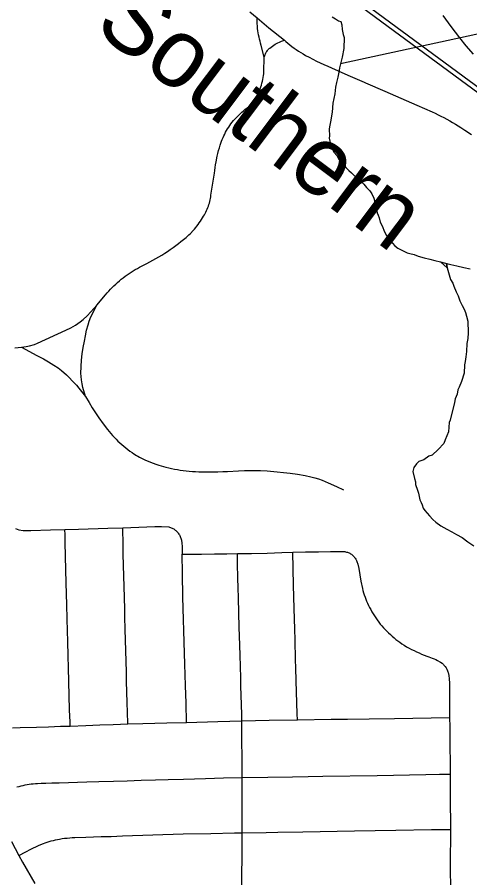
# Model space of a CAD drawing. Extents: x 0 to 34, y -1.2 to 22.
# Drawn here: x 6.951 to 7.322, y 18.066 to 18.774 of the extents above; entities that cross this region are included whole.
import ezdxf

# ---------------------------------------------------------------- set-up
doc = ezdxf.new("R2010")
doc.units = 0
for name, color, linetype in [('GM_X_City_Street', 7, 'Continuous'), ('GM_X_County_Road', 7, 'Continuous'), ('GM_X_Rail_Line', 7, 'Continuous'), ('GM_X_Rail_Line_Text', 7, 'Continuous'), ('GM_X_State_Route', 7, 'Continuous'), ('SH_Border', 7, 'Continuous'), ('SH_Data', 7, 'Continuous')]:
    doc.layers.add(name, color=color, linetype=linetype)

msp = doc.modelspace()

# ---------------------------------------------------------------- linework, layer by layer
at = {"layer": 'GM_X_City_Street'}
for points in [[(7.15357, 18.74058), (7.15114, 18.75038), (7.15065, 18.75207), (7.15018, 18.75376), (7.14976, 18.75546), (7.14937, 18.75717), (7.14902, 18.75889), (7.14871, 18.76062), (7.14844, 18.76235), (7.14821, 18.76409), (7.14801, 18.76583), (7.14781, 18.76858), (7.14768, 18.77296)], [(6.94876, 18.50187), (6.95415, 18.5024), (6.9581, 18.50301), (6.96084, 18.50352), (6.96487, 18.50464), (6.96748, 18.50559), (6.99072, 18.51625), (6.99482, 18.51826), (6.99872, 18.52057), (7.00246, 18.52317), (7.00482, 18.52506), (7.00816, 18.52814), (7.01128, 18.53145), (7.01601, 18.53697), (7.02321, 18.54547), (7.02454, 18.54699), (7.02589, 18.54849), (7.02728, 18.54995), (7.02869, 18.55139), (7.03014, 18.5528), (7.0316, 18.55419), (7.0331, 18.55555), (7.03462, 18.55687), (7.03617, 18.55816), (7.03774, 18.55942), (7.03934, 18.56062), (7.04096, 18.56178), (7.0426, 18.56291), (7.04426, 18.564), (7.04595, 18.56506), (7.04766, 18.56608), (7.04939, 18.56707), (7.05115, 18.56802), (7.05724, 18.57108), (7.05975, 18.5724), (7.06224, 18.57376), (7.0647, 18.57515), (7.06715, 18.57658), (7.06957, 18.57806), (7.07197, 18.57957), (7.07424, 18.58107), (7.07649, 18.58261), (7.0787, 18.58418), (7.0809, 18.58579), (7.08307, 18.58744), (7.08521, 18.58912), (7.08732, 18.59084), (7.08941, 18.59259), (7.09062, 18.59365), (7.09181, 18.59475), (7.09296, 18.59588), (7.0952, 18.59821), (7.09628, 18.59942), (7.09732, 18.60066), (7.09833, 18.60191), (7.09932, 18.60319), (7.10027, 18.6045), (7.10119, 18.60583), (7.10208, 18.60718), (7.10294, 18.60855), (7.10376, 18.60994), (7.10443, 18.61108), (7.10507, 18.61223), (7.10567, 18.6134), (7.10624, 18.61459), (7.10677, 18.6158), (7.10727, 18.61702), (7.10773, 18.61827), (7.10815, 18.61952), (7.10854, 18.62078), (7.10888, 18.62206), (7.10919, 18.62335), (7.10946, 18.62465), (7.10969, 18.62595), (7.10988, 18.62726), (7.11269, 18.64527), (7.11299, 18.64762), (7.11333, 18.64996), (7.1137, 18.6523), (7.11411, 18.65464), (7.11505, 18.65928), (7.11558, 18.66159), (7.11614, 18.66389), (7.11674, 18.66619), (7.11739, 18.66847), (7.11792, 18.67001), (7.1185, 18.67154), (7.11911, 18.67305), (7.11976, 18.67456), (7.12045, 18.67604), (7.12117, 18.6775), (7.12193, 18.67895), (7.12272, 18.68038), (7.12355, 18.68179), (7.12441, 18.68317), (7.12531, 18.68454), (7.12624, 18.68588), (7.1272, 18.6872), (7.12845, 18.68864), (7.12973, 18.69005), (7.13105, 18.69144), (7.13239, 18.69279), (7.13377, 18.6941), (7.13517, 18.69539), (7.13661, 18.69664), (7.13808, 18.69786), (7.13957, 18.69904), (7.14109, 18.70019), (7.14395, 18.70285), (7.14461, 18.70354), (7.14523, 18.70426), (7.14583, 18.70501), (7.14639, 18.70578), (7.14692, 18.70658), (7.14741, 18.70739), (7.14786, 18.70823), (7.14828, 18.70908), (7.14866, 18.70996), (7.14986, 18.71323), (7.15038, 18.71473), (7.15086, 18.71624), (7.15131, 18.71777), (7.15171, 18.7193), (7.15209, 18.72085), (7.15242, 18.7224), (7.15271, 18.72396), (7.15296, 18.72553), (7.15317, 18.72711), (7.15334, 18.72869), (7.15357, 18.74058), (7.15399, 18.74205), (7.15426, 18.74276), (7.15456, 18.74346), (7.15491, 18.74414), (7.15529, 18.7448), (7.15572, 18.74543), (7.15617, 18.74604), (7.15666, 18.74663), (7.15718, 18.74718), (7.15774, 18.74771), (7.15832, 18.7482), (7.15933, 18.74901), (7.16038, 18.74979), (7.16146, 18.75053), (7.16256, 18.75123), (7.16368, 18.75188), (7.16483, 18.75249), (7.16622, 18.75311), (7.16785, 18.75374), (7.17014, 18.75456)], [(7.00687, 18.46178), (7.0046, 18.4693), (7.00395, 18.47238), (7.00347, 18.47548), (7.0031, 18.48089), (7.00344, 18.49172), (7.00408, 18.49691), (7.00491, 18.50208), (7.00594, 18.50722), (7.00676, 18.51177), (7.00775, 18.51629), (7.00889, 18.52077), (7.00973, 18.52366), (7.01125, 18.52727), (7.01601, 18.53697)], [(6.95415, 18.5024), (6.96686, 18.49553), (6.97219, 18.49277), (6.97652, 18.49032), (6.98075, 18.48772), (6.98428, 18.48532), (6.9871, 18.48315), (6.99112, 18.47963), (6.99364, 18.47711), (6.996, 18.47471), (6.99929, 18.47125), (7.00145, 18.46882), (7.00687, 18.46178), (7.00971, 18.45681), (7.01224, 18.45252), (7.01498, 18.44845), (7.01785, 18.44436), (7.02134, 18.4395), (7.02496, 18.43473), (7.02766, 18.43142), (7.02906, 18.4298), (7.0305, 18.42823), (7.03198, 18.42669), (7.0335, 18.42518), (7.03508, 18.42373), (7.03668, 18.42232), (7.03831, 18.42094), (7.03997, 18.4196), (7.04165, 18.41828), (7.04335, 18.41699), (7.04508, 18.41573), (7.0466, 18.41473), (7.04865, 18.41348), (7.0497, 18.41286), (7.05128, 18.41199), (7.05289, 18.41116), (7.05453, 18.41037), (7.05618, 18.40963), (7.05979, 18.40808), (7.06162, 18.40737), (7.06531, 18.40604), (7.06718, 18.40543), (7.07095, 18.40432), (7.07285, 18.40381), (7.07519, 18.40325), (7.07755, 18.40273), (7.07991, 18.40225), (7.08228, 18.40182), (7.08466, 18.40143), (7.08704, 18.4011), (7.08944, 18.4008), (7.09203, 18.40053), (7.09464, 18.40031), (7.09724, 18.40012), (7.09985, 18.39999), (7.10246, 18.39989), (7.11559, 18.39995), (7.11955, 18.40009), (7.1235, 18.40026), (7.13238, 18.40074), (7.13729, 18.40094), (7.14221, 18.4011), (7.15048, 18.401), (7.15598, 18.40074), (7.15873, 18.40055), (7.1641, 18.40004), (7.16947, 18.39946), (7.17484, 18.39882), (7.18105, 18.39793), (7.18723, 18.39687), (7.1919, 18.39593), (7.19504, 18.39512), (7.19814, 18.39415), (7.20119, 18.39303), (7.20621, 18.39083), (7.21297, 18.38782), (7.21874, 18.38526)], [(6.94931, 18.35333), (6.95201, 18.35225), (6.95562, 18.35172), (6.96198, 18.3518), (6.97804, 18.35221), (6.98985, 18.35246), (7.00111, 18.35287), (7.02517, 18.35368), (7.03736, 18.35401), (7.06379, 18.35491), (7.06911, 18.35501), (7.07521, 18.35479), (7.07592, 18.35458), (7.07662, 18.35433), (7.07729, 18.35405), (7.07796, 18.35373), (7.0786, 18.35338), (7.07923, 18.35299), (7.07984, 18.35257), (7.08043, 18.35212), (7.08098, 18.35164), (7.08206, 18.3506), (7.08257, 18.35003), (7.08306, 18.34944), (7.08351, 18.34882), (7.08392, 18.34817), (7.0843, 18.3475), (7.08464, 18.34682), (7.08494, 18.34611), (7.0852, 18.34539), (7.08543, 18.34466), (7.0856, 18.34391), (7.08574, 18.34316), (7.08589, 18.34192), (7.08602, 18.34074), (7.0861, 18.33922), (7.08619, 18.33227), (7.10209, 18.33237), (7.11289, 18.33247), (7.12286, 18.3326), (7.13158, 18.33273), (7.1432, 18.33292), (7.15595, 18.33324), (7.16811, 18.33363), (7.17697, 18.33391), (7.18761, 18.33414), (7.19812, 18.33433), (7.20795, 18.33447), (7.21759, 18.33458), (7.21905, 18.33449), (7.21978, 18.33439), (7.22049, 18.33424), (7.22121, 18.33406), (7.2219, 18.33385), (7.22259, 18.3336), (7.22327, 18.33331), (7.22392, 18.33298), (7.22456, 18.33263), (7.22518, 18.33224), (7.22578, 18.33176), (7.22634, 18.33125), (7.22688, 18.33071), (7.22739, 18.33015), (7.22788, 18.32955), (7.22832, 18.32894), (7.22874, 18.3283), (7.22947, 18.32696), (7.23004, 18.32555), (7.23028, 18.32482), (7.23047, 18.32408), (7.23123, 18.32038), (7.233, 18.31005), (7.2342, 18.30411), (7.23469, 18.30234), (7.23521, 18.30057), (7.23578, 18.29881), (7.23638, 18.29707), (7.23702, 18.29535), (7.23769, 18.29363), (7.2384, 18.29194), (7.23915, 18.29025), (7.2401, 18.28848), (7.24108, 18.28673), (7.24209, 18.28501), (7.24314, 18.2833), (7.24422, 18.28161), (7.24534, 18.27994), (7.24893, 18.27487), (7.24974, 18.27393), (7.25022, 18.27336), (7.25156, 18.27188), (7.25293, 18.27042), (7.25433, 18.26899), (7.25576, 18.26759), (7.25722, 18.26622), (7.25871, 18.26489), (7.26023, 18.26358), (7.26178, 18.26231), (7.26335, 18.26107), (7.26495, 18.25987), (7.26661, 18.25866), (7.26861, 18.25744), (7.27058, 18.25627), (7.27258, 18.25516), (7.2746, 18.25408), (7.27664, 18.25304), (7.27869, 18.25204), (7.28077, 18.25109), (7.28287, 18.25017), (7.28499, 18.2493), (7.28717, 18.24846), (7.28873, 18.24796), (7.29019, 18.24745), (7.29164, 18.24689), (7.29307, 18.24628), (7.29448, 18.24564), (7.29587, 18.24495), (7.2979, 18.24385), (7.29851, 18.24348), (7.29966, 18.24265), (7.30071, 18.24171), (7.30121, 18.2412), (7.30212, 18.24011), (7.30293, 18.23894), (7.30361, 18.2377), (7.30417, 18.2364), (7.3044, 18.23573), (7.30459, 18.23507), (7.30509, 18.23256), (7.30547, 18.22998), (7.3056, 18.22869), (7.30569, 18.22739), (7.30585, 18.19808), (7.30596, 18.19034), (7.30604, 18.18391), (7.30634, 18.1516), (7.30626, 18.13312), (7.3066, 18.1061), (7.30641, 18.07656), (7.30663, 18.05504)], [(6.99422, 18.19107), (6.99413, 18.1947), (6.99396, 18.19899), (6.99379, 18.20474), (6.99293, 18.2388), (6.99269, 18.24862), (6.99233, 18.26056), (6.99202, 18.2694), (6.99179, 18.27922), (6.9914, 18.29064), (6.99105, 18.30868), (6.9908, 18.31948), (6.99018, 18.34191), (6.99, 18.34831), (6.98985, 18.35246)], [(7.04151, 18.19296), (7.04127, 18.20268), (7.04112, 18.20977), (7.04084, 18.21943), (7.04058, 18.22736), (7.04042, 18.23523), (7.0395, 18.27077), (7.0392, 18.28044), (7.03904, 18.28736), (7.03854, 18.30574), (7.0383, 18.31424), (7.0381, 18.32333), (7.03785, 18.33224), (7.03774, 18.33979), (7.03736, 18.35401)], [(7.08986, 18.19409), (7.0895, 18.20988), (7.08901, 18.22447), (7.08847, 18.24182), (7.08817, 18.25104), (7.08688, 18.29699), (7.08646, 18.31652), (7.08619, 18.33227)], [(7.13534, 18.05407), (7.13541, 18.09801), (7.13547, 18.10338), (7.13539, 18.11077), (7.13542, 18.14882), (7.13525, 18.19537), (7.13517, 18.20054), (7.1349, 18.20847), (7.13447, 18.22424), (7.13428, 18.23072), (7.13411, 18.24008), (7.13391, 18.24919), (7.13361, 18.25733), (7.13327, 18.26513), (7.13308, 18.27208), (7.13245, 18.2965), (7.13218, 18.3046), (7.13202, 18.31256), (7.13175, 18.32475), (7.13158, 18.33273)], [(7.18093, 18.19623), (7.18077, 18.20123), (7.17989, 18.2281), (7.17958, 18.23887), (7.17942, 18.24553), (7.17889, 18.26203), (7.17862, 18.27054), (7.17845, 18.27905), (7.17825, 18.28776), (7.17771, 18.30677), (7.17697, 18.33391)], [(6.94681, 18.18958), (6.95328, 18.18978), (6.96647, 18.19019), (6.97653, 18.19047), (6.98635, 18.19083), (6.99422, 18.19107), (7.00699, 18.19153), (7.01852, 18.19201), (7.02949, 18.19242), (7.04151, 18.19296), (7.05379, 18.1932), (7.06389, 18.1935), (7.07355, 18.19376), (7.08986, 18.19409), (7.11545, 18.1948), (7.13525, 18.19537), (7.15759, 18.19578), (7.18093, 18.19623), (7.2086, 18.19658), (7.22208, 18.19677), (7.23985, 18.19705), (7.26056, 18.19734), (7.30585, 18.19808)], [(6.95055, 18.14104), (6.95223, 18.1415), (6.95391, 18.14192), (6.95561, 18.1423), (6.95733, 18.14264), (6.95899, 18.14296), (6.96064, 18.14322), (6.96231, 18.14345), (6.96382, 18.14362), (6.96565, 18.14379), (6.96733, 18.1439), (6.97045, 18.14404), (6.97436, 18.14413), (6.9793, 18.14429), (6.98515, 18.14445), (7.00795, 18.14519), (7.01788, 18.14546), (7.02973, 18.14586), (7.04096, 18.14618), (7.05244, 18.14653), (7.0644, 18.14691), (7.0746, 18.14726), (7.08735, 18.14754), (7.10544, 18.14809), (7.12019, 18.14842), (7.13542, 18.14882), (7.15651, 18.14906), (7.17681, 18.14937), (7.1897, 18.14961), (7.20185, 18.14982), (7.24626, 18.15044), (7.28645, 18.15121), (7.29767, 18.15146), (7.30634, 18.1516)], [(6.95217, 18.08458), (6.95784, 18.08763), (6.96189, 18.08981), (6.96412, 18.09096), (6.96611, 18.09192), (6.96811, 18.09285), (6.97014, 18.09371), (6.97219, 18.09454), (6.9738, 18.09514), (6.97543, 18.09571), (6.97708, 18.09622), (6.97873, 18.09671), (6.9804, 18.09714), (6.98208, 18.09754), (6.98376, 18.09789), (6.98547, 18.0982), (6.98756, 18.09853), (6.98966, 18.09881), (6.99176, 18.09906), (6.99387, 18.09925), (6.99597, 18.09939), (6.99811, 18.09949), (7.00721, 18.09981), (7.01967, 18.10018), (7.02784, 18.10041), (7.03726, 18.10078), (7.08691, 18.10239), (7.10978, 18.10288), (7.12916, 18.10329), (7.13547, 18.10338), (7.1551, 18.10362), (7.16475, 18.10382), (7.18533, 18.10425), (7.22786, 18.10483), (7.26171, 18.10545), (7.29092, 18.10598), (7.3066, 18.1061)]]:
    msp.add_lwpolyline(points, dxfattribs=at)
at = {"layer": 'GM_X_County_Road'}
msp.add_lwpolyline([(6.94595, 18.09607), (6.95217, 18.08458), (6.95509, 18.07917), (6.96528, 18.06156)], dxfattribs=at)
at = {"layer": 'GM_X_Rail_Line'}
for points in [[(7.37986, 18.67392), (6.76814, 19.12466)], [(7.38211, 18.67689), (6.77035, 19.12766)], [(7.32561, 18.74301), (7.31947, 18.75003), (7.31413, 18.75661), (7.30704, 18.76575), (7.30046, 18.77496)]]:
    msp.add_lwpolyline(points, dxfattribs=at)
at = {"layer": 'GM_X_State_Route'}
msp.add_lwpolyline([(7.14171, 18.7779), (7.14768, 18.77296), (7.15744, 18.76487), (7.17014, 18.75456), (7.17125, 18.75367), (7.17293, 18.75225), (7.17465, 18.75086), (7.1764, 18.74951), (7.17816, 18.74819), (7.17995, 18.74691), (7.18177, 18.74566), (7.18362, 18.74445), (7.18548, 18.74328), (7.18737, 18.74214), (7.19038, 18.74055), (7.19342, 18.739), (7.19648, 18.73749), (7.19955, 18.73603), (7.20265, 18.73461), (7.20576, 18.73322), (7.20889, 18.73187), (7.2224, 18.72589), (7.23581, 18.72006), (7.23689, 18.71959), (7.25263, 18.71285), (7.26576, 18.7071), (7.27905, 18.70114), (7.29147, 18.69565), (7.29392, 18.69454), (7.29636, 18.69339), (7.29877, 18.69221), (7.30118, 18.69099), (7.30356, 18.68973), (7.30592, 18.68844), (7.30826, 18.68711), (7.31059, 18.68575), (7.31289, 18.68436), (7.31517, 18.68292), (7.31842, 18.68079), (7.32383, 18.67717)], dxfattribs=at)
at = {"layer": 'SH_Border'}
msp.add_lwpolyline([(7.36768, 18.77892), (7.4506, 18.77862), (7.48368, 18.77949), (7.53623, 18.7757), (7.55485, 18.77673), (7.5547, 18.73944), (7.56168, 18.70796), (7.56098, 18.68093), (7.54558, 18.66891), (7.53908, 18.64751), (7.53455, 18.62232), (7.52458, 18.6043), (7.51791, 18.61637), (7.50416, 18.62036), (7.4617, 18.65854), (7.46182, 18.67415), (7.43414, 18.66879), (7.36139, 18.74534), (7.35384, 18.76502), (7.21626, 18.73522)], dxfattribs=at)
at = {"layer": 'SH_Data'}
for points in [[(7.20954, 18.77393), (7.21224, 18.77207), (7.21454, 18.77058), (7.21646, 18.76985), (7.21726, 18.7672), (7.2177, 18.7634), (7.21853, 18.75923), (7.21933, 18.75695), (7.2191, 18.74782), (7.2177, 18.74057), (7.21626, 18.73522)], [(7.21626, 18.73522), (7.21556, 18.73179), (7.21485, 18.72835), (7.21416, 18.72416), (7.21309, 18.71995), (7.21201, 18.71613), (7.21172, 18.71042), (7.20995, 18.70279), (7.2093, 18.69555), (7.20791, 18.68753), (7.20722, 18.68334), (7.20687, 18.68143), (7.20734, 18.67611), (7.20699, 18.6742), (7.20864, 18.66662), (7.21099, 18.66247), (7.21331, 18.65984), (7.21527, 18.65644), (7.21837, 18.65268), (7.2207, 18.65005), (7.22302, 18.64742), (7.22534, 18.64555), (7.22727, 18.64368), (7.22959, 18.64143), (7.23267, 18.63881), (7.23538, 18.63619), (7.2377, 18.63356), (7.24041, 18.63094), (7.24197, 18.6283), (7.24355, 18.62489), (7.24518, 18.61845), (7.24641, 18.61276), (7.2472, 18.61087), (7.248, 18.6086), (7.24881, 18.60519), (7.25078, 18.60141), (7.25198, 18.59762), (7.25394, 18.59423), (7.25549, 18.59235), (7.25705, 18.59009), (7.25899, 18.58783), (7.26093, 18.58558), (7.26324, 18.58371), (7.27091, 18.58002), (7.2732, 18.57929), (7.27663, 18.57858), (7.28008, 18.57711), (7.28505, 18.57566), (7.28963, 18.57458), (7.29383, 18.5735), (7.29841, 18.57243), (7.30262, 18.57135), (7.30682, 18.57027), (7.31178, 18.5692), (7.31751, 18.56777), (7.32285, 18.5667)], [(7.29841, 18.57243), (7.30382, 18.56756), (7.30338, 18.57136), (7.30382, 18.56756), (7.30502, 18.56378), (7.30664, 18.55809), (7.30859, 18.55508), (7.30939, 18.55242), (7.31137, 18.54789), (7.31295, 18.54449), (7.31415, 18.54032), (7.31612, 18.53654), (7.31769, 18.53352), (7.31887, 18.53088), (7.31968, 18.52784), (7.32089, 18.52367), (7.32095, 18.52025), (7.32099, 18.51759), (7.32105, 18.51417), (7.32074, 18.50959), (7.32005, 18.5054), (7.31977, 18.49893), (7.31909, 18.49435), (7.31877, 18.49054), (7.31805, 18.48787), (7.31778, 18.48101), (7.31562, 18.47413), (7.31379, 18.46954), (7.31269, 18.46724), (7.31198, 18.4638), (7.31052, 18.45998), (7.30981, 18.45692), (7.30625, 18.44241), (7.30552, 18.4405), (7.30488, 18.43288), (7.30232, 18.42637), (7.30123, 18.42331), (7.29637, 18.41829), (7.2915, 18.41366), (7.28885, 18.41286), (7.28472, 18.40975), (7.28055, 18.40855), (7.27868, 18.40662), (7.27645, 18.40354), (7.27575, 18.40011), (7.27698, 18.39442), (7.27779, 18.39177), (7.27782, 18.38948), (7.27942, 18.38494), (7.28022, 18.38229), (7.28145, 18.37698), (7.28263, 18.37471), (7.28342, 18.37282), (7.28423, 18.37017), (7.2854, 18.36828), (7.28927, 18.36378), (7.29198, 18.36077), (7.29468, 18.35853), (7.29854, 18.35554), (7.30352, 18.35295), (7.30774, 18.35073), (7.31158, 18.3485), (7.31619, 18.34591), (7.32081, 18.34255), (7.32581, 18.3392)]]:
    msp.add_lwpolyline(points, dxfattribs=at)

# ---------------------------------------------------------------- texts
at = {"layer": 'GM_X_Rail_Line_Text'}
msp.add_text('Southern', height=0.056629, rotation=323.10237, dxfattribs=at).set_placement((7.01223, 18.76373))

doc.saveas('drawing.dxf')
